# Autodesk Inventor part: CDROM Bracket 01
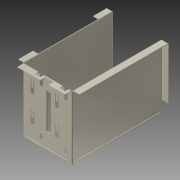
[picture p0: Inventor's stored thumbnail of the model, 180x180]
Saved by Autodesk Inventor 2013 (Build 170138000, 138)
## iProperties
Created: 2007-02
Part Number: CDROM Bracket 01
Material: Allgemein
Document SubType Name: Sheet Metal
Designer: Autodesk, Inc.
Mass: 48.1441 g
Surface Area: 981.248 cm^2
Volume: 48.1441 cm^3
Density: 1 g/cm^3
Flat Pattern Width: 12.4144 cm
Flat Pattern Length: 41.0906 cm
Flat Pattern Area: 510.116 cm^2
Sheet Metal Rule: 1 mm
Sheet Metal Width: 124.144 mm
Sheet Metal Length: 410.906 mm
Sheet Metal Area: 51011.640 mm^2
Author: Autodesk, Inc.
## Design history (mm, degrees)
node "Contour Flange1"
node "Flange1"
node "Flange2"
node "Flange3"
node "Flange4"
node "Flange5"
feature "Corner6" dims "d51" = 4 (= CornerReliefSize), "d52" = 0.5 (= BendRadius), "d53" = 1 (= Thickness), "d54" = 0, "Thickness" = 1
feature "Corner8" dims "d91" = 4 (= CornerReliefSize), "d92" = 0.5 (= BendRadius), "d93" = 1 (= Thickness), "d94" = 0, "Thickness" = 1
cut "Cut1" dims "d80" = 1 (= Thickness), "d81" = 0
pattern_linear "Rectangular Pattern1" dims "d84" = 42
cut "Cut2" dims "d89" = 1 (= Thickness), "d90" = 0
sketch "Sketch9" dims "d95" = 10
  geometry: L1 (0, 82)-(0, 0); L2 (13, 54.2)-(17.6, 54.2); L3 (17.6, 54.2)-(17.6, 48.8); L4 (17.6, 48.8)-(13, 48.8); L5 (13, 48.8)-(13, 54.2); L6 (28.5, 42)-(88.5, 42); L7 (88.5, 42)-(88.5, 35); L8 (88.5, 35)-(28.5, 35); L9 (28.5, 35)-(28.5, 42); L10 (28.5, 70)-(28.5, 64); L11 (93.5, 69.5)-(93.5, 69.5); L12 (83, 65)-(93, 65); L13 (93, 69)-(83, 69); L14 (83, 69)-(83, 65); L15 (93, 70)-(73.5, 70); L16 (73.5, 70)-(73.5, 64); L17 (73.5, 64)-(93, 64); L18 (38, 69)-(38, 65); L19 (28.5, 64)-(48, 64); L20 (48, 70)-(28.5, 70); L21 (48, 69)-(38, 69); L22 (38, 65)-(48, 65); L23 (48.5, 64.5)-(48.5, 64.5); L24 (48.5, 69.5)-(48.5, 69.5); L25 (93.5, 64.5)-(93.5, 64.5); L26 (108.5, 14.2)-(108.5, 46.8) reference; L27 (108.5, 56.2)-(108.5, 82) reference; L28 (0, 82)-(108.5, 82) reference; A1 r 0.5 centre (93, 69.5) between (93, 69) and (93.5, 69.5); A2 r 0.5 centre (93, 69.5) between (93.5, 69.5) and (93, 70); A3 r 2 centre (83, 67) between (83, 69) and (83, 65); A4 r 2 centre (38, 67) between (38, 69) and (38, 65); A5 r 0.5 centre (48, 64.5) between (48, 64) and (48.5, 64.5); A6 r 0.5 centre (48, 64.5) between (48.5, 64.5) and (48, 65); A7 r 0.5 centre (48, 69.5) between (48, 69) and (48.5, 69.5); A8 r 0.5 centre (48, 69.5) between (48.5, 69.5) and (48, 70); A9 r 0.5 centre (93, 64.5) between (93.5, 64.5) and (93, 65); A10 r 0.5 centre (93, 64.5) between (93, 64) and (93.5, 64.5); 6 further points
  constraints: 50 end point, 20 point on circle, 16 tangent, 12 parallel, 10 centre point, 8 collinear, 7 equal radius, 6 horizontal, 6 midpoint, 6 perpendicular, 6 vertical alignment, 4 point on line, 8 other
  dimensions: "d96" = 13 distance between parallel lines of L1 L5; "d99" = 60 distance of L7.end L8.end; "d100" = 6 distance of point (93.5, 64) point (93.5, 70); "d102" = 20 distance of L16.end point (93.5, 64); "d103" = 7 distance between parallel lines of L8 L6; "d104" = 1 distance between parallel lines of L20 L21; "d105" = 1 distance between parallel lines of L19 L22 (= d104); "d106" = 0.5 radius of A8; "d107" = 10 distance of L18.end L22.end; "d109" = 25 distance from line of L16 L24.end; "d110" = 20 distance between parallel lines of L7 L26; "d111" = 15 distance from line of L27 point (93.5, 70); "d112" = 12 distance between parallel lines of L28 L15; "d113" = 40 distance between parallel lines of L28 L6; "d114" = 30.5 distance from line of L28 point (13, 51.5)
cut "Cut3" dims "d115" = 1 (= Thickness), "d116" = 0
node "Flange6"
cut "Cut4" dims "d126" = 1 (= Thickness), "d127" = 0
pattern_linear "Rectangular Pattern2" dims "d130" = 42
feature "Hem1" dims "d131" = 1 (= BendReliefWidth), "d132" = 0.5 (= BendReliefDepth), "d133" = 2 (= MinimumRemnant), "d134" = 0.5 (= BendRadius), "d135" = 5, "d136" = 5, "d137" = 4 (= 4 x Thickness), "d138" = 0.5 (= 0.5 x Thickness), "d139" = 0.25 (= 0.5 x d138), "SeamGap" = 0.01, "Thickness" = 1
feature "Hem2" dims "d140" = 1 (= BendReliefWidth), "d141" = 0.5 (= BendReliefDepth), "d142" = 2 (= MinimumRemnant), "d143" = 0.5 (= BendRadius), "d144" = 4 (= 4 x Thickness), "d145" = 0.5 (= 0.5 x Thickness), "d146" = 0.25 (= 0.5 x d145), "d156" = 5, "d157" = 5, "SeamGap" = 0.01, "Thickness" = 1
feature "Hem3" dims "d147" = 1 (= BendReliefWidth), "d148" = 0.5 (= BendReliefDepth), "d149" = 2 (= MinimumRemnant), "d150" = 0.5 (= BendRadius), "d151" = 4 (= 4 x Thickness), "d152" = 0.5 (= 0.5 x Thickness), "d153" = 0.25 (= 0.5 x d152), "d154" = 5, "d155" = 5, "SeamGap" = 0.01, "Thickness" = 1
body "Solid1"
sketch "Sketch1"
  geometry: L1 (-77, 41.5)-(77, 41.5); L2 (77, 41.5)-(77, -41.5); L3 (77, -41.5)-(-77, -41.5); L4 (-77, -41.5)-(-77, 41.5); L5 (-77, 41.5)-(77, -41.5); 2 further points
  constraints: 10 end point, 2 parallel, 1 coincident, 1 horizontal, 1 midpoint, 1 perpendicular
  dimensions: "d0" = 154 distance of L1.start L1.end; "d1" = 83 distance of L3.end L1.start
face "Plate1" dims "d2" = 1 (= BendReliefWidth), "d3" = 0.5 (= BendReliefDepth), "d4" = 2 (= MinimumRemnant), "d5" = 0.5 (= BendRadius), "d6" = 110, "d7" = 0.5 (= BendRadius), "d8" = 1, "d9" = 4 (= CornerReliefSize), "d10" = 1 (= Thickness), "d158" = 1 (= JacobiRadiusSize), "SeamGap" = 0.01, "Thickness" = 1
bend "Bend1" dims "d2" = 1 (= BendReliefWidth), "d3" = 0.5 (= BendReliefDepth), "d4" = 2 (= MinimumRemnant), "d5" = 0.5 (= BendRadius), "d7" = 0.5 (= BendRadius), "d8" = 1, "SeamGap" = 0.01, "Thickness" = 1
feature "Corner1" dims "d8" = 1, "d9" = 4 (= CornerReliefSize), "d10" = 1 (= Thickness), "d158" = 1 (= JacobiRadiusSize)
sketch "Sketch2"
  geometry: L1 through (0, -41) direction (3.25e-16, 1); L2 through (-6, 0) direction (-1, -1.22e-48); L3 (-12, 0)-(-12, -82); L4 (-12, -82)-(0, -82)
  constraints: 6 end point, 1 horizontal, 1 perpendicular, 1 vertical
face "Plate2" dims "d11" = 1 (= BendReliefWidth), "d12" = 0.5 (= BendReliefDepth), "d13" = 2 (= MinimumRemnant), "d14" = 0.5 (= BendRadius), "d15" = 12, "d16" = 90 deg, "d17" = 0.5 (= BendRadius), "d18" = 4 (= CornerReliefSize), "d19" = 1 (= Thickness), "d159" = 1 (= JacobiRadiusSize), "SeamGap" = 0.01, "Thickness" = 1
bend "Bend2" dims "d11" = 1 (= BendReliefWidth), "d12" = 0.5 (= BendReliefDepth), "d13" = 2 (= MinimumRemnant), "d14" = 0.5 (= BendRadius), "d15" = 12, "d16" = 90 deg, "d17" = 0.5 (= BendRadius), "SeamGap" = 0.01, "Thickness" = 1
feature "Corner2" dims "d15" = 12, "d16" = 90 deg, "d18" = 4 (= CornerReliefSize), "d19" = 1 (= Thickness), "d159" = 1 (= JacobiRadiusSize)
sketch "Sketch3"
  geometry: L1 (-153.5, -1)-(-128.5, -1); L2 (-128.5, -1)-(-128.5, 10); L3 (-128.5, 10)-(-153.5, 10); L4 (-153.5, 10)-(-153.5, -1)
  constraints: 8 end point
face "Plate3" dims "d20" = 1 (= BendReliefWidth), "d21" = 0.5 (= BendReliefDepth), "d22" = 2 (= MinimumRemnant), "d23" = 0.5 (= BendRadius), "d24" = 25, "d25" = 0, "d26" = 10, "d27" = 90 deg, "d28" = 0.5 (= BendRadius), "d29" = 4 (= CornerReliefSize), "d30" = 1 (= Thickness), "d160" = 1 (= JacobiRadiusSize), "SeamGap" = 0.01, "Thickness" = 1
bend "Bend3" dims "d20" = 1 (= BendReliefWidth), "d21" = 0.5 (= BendReliefDepth), "d22" = 2 (= MinimumRemnant), "d23" = 0.5 (= BendRadius), "d26" = 10, "d27" = 90 deg, "d28" = 0.5 (= BendRadius), "SeamGap" = 0.01, "Thickness" = 1
feature "Corner3" dims "d26" = 10, "d27" = 90 deg, "d29" = 4 (= CornerReliefSize), "d30" = 1 (= Thickness), "d160" = 1 (= JacobiRadiusSize)
sketch "Sketch4"
  geometry: L1 (0, -1)-(-25, -1); L2 (-25, -1)-(-25, 10); L3 (-25, 10)-(0, 10); L4 (0, 10)-(0, -1)
  constraints: 8 end point
face "Plate4" dims "d31" = 1 (= BendReliefWidth), "d32" = 0.5 (= BendReliefDepth), "d33" = 2 (= MinimumRemnant), "d34" = 0.5 (= BendRadius), "d35" = 25, "d36" = 0, "d37" = 10, "d38" = 90 deg, "d39" = 0.5 (= BendRadius), "d40" = 4 (= CornerReliefSize), "d41" = 1 (= Thickness), "d161" = 1 (= JacobiRadiusSize), "SeamGap" = 0.01, "Thickness" = 1
bend "Bend4" dims "d31" = 1 (= BendReliefWidth), "d32" = 0.5 (= BendReliefDepth), "d33" = 2 (= MinimumRemnant), "d34" = 0.5 (= BendRadius), "d37" = 10, "d38" = 90 deg, "d39" = 0.5 (= BendRadius), "SeamGap" = 0.01, "Thickness" = 1
feature "Corner4" dims "d37" = 10, "d38" = 90 deg, "d40" = 4 (= CornerReliefSize), "d41" = 1 (= Thickness), "d161" = 1 (= JacobiRadiusSize)
sketch "Sketch5"
  geometry: L1 through (0, 54.25) direction (0, -1); L2 through (5, 0) direction (1, 0); L3 (10, 0)-(10, 108.5); L4 (10, 108.5)-(0, 108.5)
  constraints: 6 end point, 1 horizontal, 1 perpendicular, 1 vertical
face "Plate5" dims "d42" = 1 (= BendReliefWidth), "d43" = 0.5 (= BendReliefDepth), "d44" = 2 (= MinimumRemnant), "d45" = 0.5 (= BendRadius), "d46" = 10, "d47" = 90 deg, "d48" = 0.5 (= BendRadius), "d49" = 4 (= CornerReliefSize), "d50" = 1 (= Thickness), "d162" = 1 (= JacobiRadiusSize), "SeamGap" = 0.01, "Thickness" = 1
bend "Bend5" dims "d42" = 1 (= BendReliefWidth), "d43" = 0.5 (= BendReliefDepth), "d44" = 2 (= MinimumRemnant), "d45" = 0.5 (= BendRadius), "d46" = 10, "d47" = 90 deg, "d48" = 0.5 (= BendRadius), "SeamGap" = 0.01, "Thickness" = 1
feature "Corner5" dims "d46" = 10, "d47" = 90 deg, "d49" = 4 (= CornerReliefSize), "d50" = 1 (= Thickness), "d162" = 1 (= JacobiRadiusSize)
sketch "Sketch6"
  geometry: L1 through (0, -44.25) direction (0, -1); L2 (0, -88.5)-(-12, -88.5); L3 (-12, -88.5)-(-12, 0); L4 through (-6, 0) direction (1, 0)
  constraints: 6 end point, 1 horizontal, 1 perpendicular, 1 vertical
face "Plate6" dims "d55" = 1 (= BendReliefWidth), "d56" = 0.5 (= BendReliefDepth), "d57" = 2 (= MinimumRemnant), "d58" = 0.5 (= BendRadius), "d61" = 12, "d62" = 90 deg, "d63" = 0.5 (= BendRadius), "d64" = 4 (= CornerReliefSize), "d65" = 1 (= Thickness), "d66" = 0, "d67" = 20, "d163" = 1 (= JacobiRadiusSize), "SeamGap" = 0.01, "Thickness" = 1
bend "Bend6" dims "d55" = 1 (= BendReliefWidth), "d56" = 0.5 (= BendReliefDepth), "d57" = 2 (= MinimumRemnant), "d58" = 0.5 (= BendRadius), "d61" = 12, "d62" = 90 deg, "d63" = 0.5 (= BendRadius), "SeamGap" = 0.01, "Thickness" = 1
feature "Corner7" dims "d61" = 12, "d62" = 90 deg, "d64" = 4 (= CornerReliefSize), "d65" = 1 (= Thickness), "d163" = 1 (= JacobiRadiusSize)
sketch "Sketch7" dims "d13" = 2 (= MinimumRemnant)
  geometry: L1 (28, 54.2)-(13, 54.2); L2 (28, 48.8)-(28, 54.2); L3 (13, 48.8)-(28, 48.8); L4 (13, 56.2)-(13, 46.8); L5 (13, 46.8)-(5, 46.8); L6 (5, 46.8)-(5, 56.2); L7 (5, 56.2)-(13, 56.2); L8 (13, 54.2)-(13, 48.8); L9 (0, 82)-(10.5, 82) reference; L10 (0, 0)-(0, 82) reference; 1 further point
  constraints: 16 end point, 4 parallel, 2 perpendicular, 1 midpoint, 1 point on line, 1 vertical alignment, 2 other
  dimensions: "d70" = 8 distance of L6.end L4.start; "d72" = 2 distance between parallel lines of L7 L1; "d73" = 2 distance between parallel lines of L5 L3 (= d72); "d74" = 15 distance of L1.start L1.end; "d76" = 23 distance from line of point (28, 51.5) L6 (derived); "d77" = 9.4 distance of L5.end L6.end; "d78" = 25.8 distance between parallel lines of L9 L7; "d79" = 5 distance between parallel lines of L10 L6
sketch "Sketch8"
  geometry: L1 (-1, 42.5)-(9, 42.5); L2 (9, 42.5)-(9, 28.5); L3 (9, 28.5)-(-1, 28.5); L4 (-1, 28.5)-(-1, 42.5); L5 (10.5, 14.2)-(10.5, 46.8) reference; L6 (0, 82)-(10.5, 82) reference
  constraints: 8 end point, 2 parallel, 1 horizontal, 1 perpendicular
  dimensions: "d85" = 14 distance of L3.end L1.start; "d86" = 10 distance of L1.start L1.end; "d87" = 1.5 distance between parallel lines of L5 L2; "d88" = 39.5 distance between parallel lines of L6 L1
sketch "Sketch10"
  geometry: L1 (0, -59.99)-(0, -0.01); L2 (0, -0.01)-(-5, -0.01); L3 (-5, -0.01)-(-5, -59.99); L4 (-5, -59.99)-(0, -59.99)
  constraints: 8 end point
face "Plate7" dims "d117" = 1 (= BendReliefWidth), "d118" = 0.5 (= BendReliefDepth), "d119" = 2 (= MinimumRemnant), "d120" = 0.5 (= BendRadius), "d121" = 5, "d122" = 90 deg, "d123" = 0.5 (= BendRadius), "d124" = 4 (= CornerReliefSize), "d125" = 1 (= Thickness), "d164" = 1 (= JacobiRadiusSize), "SeamGap" = 0.01, "Thickness" = 1
bend "Bend7" dims "d117" = 1 (= BendReliefWidth), "d118" = 0.5 (= BendReliefDepth), "d119" = 2 (= MinimumRemnant), "d120" = 0.5 (= BendRadius), "d121" = 5, "d122" = 90 deg, "d123" = 0.5 (= BendRadius), "SeamGap" = 0.01, "Thickness" = 1
feature "Corner9" dims "d121" = 5, "d122" = 90 deg, "d124" = 4 (= CornerReliefSize), "d125" = 1 (= Thickness), "d164" = 1 (= JacobiRadiusSize)
sketch "Sketch11"
  geometry: L1 (-1, 0)-(0, 0); L2 (0.5, 0)-(0.5, 2.75); L3 (0.5, 2.75)-(1.5, 2.75); L4 (1.5, 2.75)-(1.5, 0); A1 r 0.25 centre (0.25, 0) between (0, 0) and (0.5, 0); A2 r 1.25 centre (0.25, 0) between (-1, 0) and (1.5, 0)
  constraints: 8 end point, 4 point on circle
sketch "Sketch12"
  geometry: L1 (-1, 0)-(0, 0); L2 (0.5, 0)-(0.5, 2.75); L3 (0.5, 2.75)-(1.5, 2.75); L4 (1.5, 2.75)-(1.5, 0); A1 r 0.25 centre (0.25, 0) between (0, 0) and (0.5, 0); A2 r 1.25 centre (0.25, 0) between (-1, 0) and (1.5, 0); 2 further points
  constraints: 8 end point, 4 point on circle
sketch "Sketch13"
  geometry: L1 (-1, 0)-(0, 0); L2 (0.5, 0)-(0.5, 2.75); L3 (0.5, 2.75)-(1.5, 2.75); L4 (1.5, 2.75)-(1.5, 0); A1 r 0.25 centre (0.25, 0) between (0, 0) and (0.5, 0); A2 r 1.25 centre (0.25, 0) between (-1, 0) and (1.5, 0); 2 further points
  constraints: 8 end point, 4 point on circle
feature "Definition1" dims "d0" = 1 (derived)
other parameters: "BendRadius" = 0.5, "BendReliefWidth" = 1 (= Thickness), "BendReliefDepth" = 0.5 (= 0.5 x Thickness), "CornerReliefSize" = 4 (= 4 x Thickness), "MinimumRemnant" = 2 (= 2 x Thickness), "TransitionRadius" = 0.5 (= BendRadius), "JacobiRadiusSize" = 1 (= Thickness), "GapSize" = 1 (= Thickness), "BendRadius" = 0.5, "BendReliefDepth" = 0.5, "BendReliefWidth" = 1, "CornerReliefSize" = 4, "JacobiRadiusSize" = 1, "MinimumRemnant" = 2, "Thickness" = 1, "TransitionRadius" = 0.5, "GapSize" = 1
